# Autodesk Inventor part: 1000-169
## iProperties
Created: 2007-03
Part Number: 1000-169
Document SubType Name: Modeling
Designer: Andy Moles
Density: 1 g/cm^3
Mass: 11.295 g
Surface Area: 76.161 cm^2
Volume: 11.295 cm^3
Author: Andy Moles
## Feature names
1. Base1
